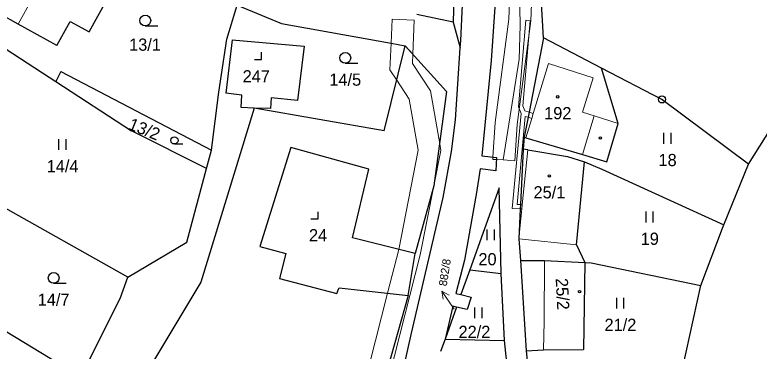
# Model space of a CAD drawing. Extents: x -739410 to -735662, y -942282 to -940043.
# Drawn here: x -738017.9 to -737914.5, y -941548.9 to -941502 of the extents above; entities that cross this region are included whole.
import ezdxf
from ezdxf.enums import TextEntityAlignment as Align

# ---------------------------------------------------------------- set-up
doc = ezdxf.new("R2010")
doc.units = 0
doc.header["$LTSCALE"] = 0.68
for name, color, linetype, lineweight in [('1', 7, 'Continuous', 25), ('13', 7, 'Continuous', 13), ('3', 7, 'Continuous', 25), ('4', 7, 'Continuous', 13), ('5', 7, 'Continuous', 25), ('7', 7, 'Continuous', 13), ('8', 7, 'Continuous', 25)]:
    doc.layers.add(name, color=color, linetype=linetype, lineweight=lineweight)
doc.layers.add('2', color=7, linetype='Continuous')

msp = doc.modelspace()

# ---------------------------------------------------------------- linework, layer by layer
at = {"layer": '1'}
for p, q in [((-737956.27, -941474.89), (-737956.99, -941503.08)), ((-737944.43, -941505.26), (-737945.75, -941484.01)), ((-737955.93, -941505.61), (-737955.53, -941496.64)), ((-737950.94, -941496.7), (-737951.7, -941508.41)), ((-738007.6, -941504.42), (-738004.51, -941498.81)), ((-737988.45, -941505.43), (-737987.03, -941500.71)), ((-737987.03, -941500.71), (-737980.87, -941503.23)), ((-738017.46, -941503.34), (-738019.6, -941502.11)), ((-737956.99, -941503.08), (-737962.06, -941502)), ((-738012.09, -941506.3), (-738017.46, -941503.34)), ((-738012.09, -941506.3), (-738010.26, -941502.95)), ((-738010.26, -941502.95), (-738007.6, -941504.42)), ((-737956.99, -941503.08), (-737956.01, -941506.61)), ((-737915.92, -941522.84), (-737904.39, -941504.29)), ((-738021.15, -941505.52), (-738014.09, -941510.1)), ((-737989.59, -941512.8), (-737988.45, -941505.43)), ((-737987.71, -941505.5), (-737988.6, -941512.93)), ((-737987.71, -941505.5), (-737977.73, -941506.41)), ((-737936.38, -941509.44), (-737944.43, -941505.26)), ((-737977.73, -941506.41), (-737978.64, -941513.98)), ((-737966.59, -941518.17), (-737963.66, -941506.35)), ((-737963.66, -941506.35), (-737957.9, -941512.7)), ((-737956.01, -941506.61), (-737955.93, -941505.61)), ((-737956.68, -941516.64), (-737956.01, -941506.61)), ((-737951.7, -941508.41), (-737953.03, -941521.67)), ((-737927.96, -941513.81), (-737936.38, -941509.44)), ((-737934.04, -941517.16), (-737936.38, -941509.44)), ((-738014.09, -941510.1), (-738012.26, -941511.3)), ((-738011.55, -941509.91), (-738012.26, -941511.3)), ((-738011.55, -941509.91), (-737990.58, -941520.89)), ((-738012.26, -941511.3), (-738001.72, -941518.17)), ((-737957.9, -941512.7), (-737959.66, -941525.86)), ((-737990.58, -941520.89), (-737989.59, -941512.8)), ((-737986.4, -941513.23), (-737988.6, -941512.93)), ((-737986.48, -941514.96), (-737986.4, -941513.23)), ((-737982.3, -941513.58), (-737982.38, -941515.08)), ((-737978.64, -941513.98), (-737982.3, -941513.58)), ((-737915.92, -941522.84), (-737927.96, -941513.81)), ((-737984.66, -941515.05), (-737992.08, -941539.27)), ((-737984.66, -941515.05), (-737986.48, -941514.96)), ((-737966.59, -941518.17), (-737984.66, -941515.05)), ((-737982.38, -941515.08), (-737984.66, -941515.05)), ((-737957.23, -941521.07), (-737956.68, -941516.64)), ((-737935.63, -941522.52), (-737934.04, -941517.16)), ((-737991.28, -941523.45), (-738001.72, -941518.17)), ((-737947.12, -941519.09), (-737947.26, -941520.75)), ((-737946.88, -941519.15), (-737947.12, -941519.09)), ((-737946.88, -941519.15), (-737939.02, -941521.48)), ((-737991.28, -941523.45), (-737990.58, -941520.89)), ((-737979.58, -941520.51), (-737983.87, -941534.28)), ((-737968.74, -941523.54), (-737979.58, -941520.51)), ((-737946.63, -941520.84), (-737947.26, -941520.75)), ((-737946.63, -941520.84), (-737941.08, -941521.74)), ((-737958.4, -941527.49), (-737957.23, -941521.07)), ((-737953.03, -941521.67), (-737950.96, -941521.9)), ((-737950.96, -941521.9), (-737951.05, -941523.76)), ((-737941.08, -941521.74), (-737938.72, -941522.52)), ((-737939.02, -941521.48), (-737935.63, -941522.52)), ((-737939.83, -941534.05), (-737938.72, -941522.52)), ((-737938.72, -941522.52), (-737936.33, -941523.54)), ((-738002.21, -941538.58), (-738029.62, -941523.14)), ((-737994.01, -941533.7), (-737991.28, -941523.45)), ((-737970.98, -941533.11), (-737968.74, -941523.54)), ((-737953.23, -941523.5), (-737953.77, -941526.76)), ((-737951.05, -941523.76), (-737953.23, -941523.5)), ((-737959.66, -941525.86), (-737962.29, -941535.26)), ((-737950.62, -941526.13), (-737954.7, -941537.56)), ((-737950.31, -941538.07), (-737950.62, -941526.13)), ((-737953.77, -941526.76), (-737955.44, -941536.18)), ((-737962.79, -941546.36), (-737958.4, -941527.49)), ((-737919.53, -941531.73), (-737919.35, -941531.28)), ((-737922.56, -941539.74), (-737919.53, -941531.73)), ((-737962.29, -941535.26), (-737970.98, -941533.11)), ((-737947.88, -941533.23), (-737947.64, -941536.23)), ((-738002.21, -941538.58), (-737994.01, -941533.7)), ((-737983.87, -941534.28), (-737980.26, -941535.26)), ((-737939.83, -941534.05), (-737938.68, -941536.52)), ((-737980.26, -941535.26), (-737981.16, -941538.76)), ((-737963.27, -941541.12), (-737962.29, -941535.26)), ((-738008.8, -941552.44), (-738035.99, -941536)), ((-737955.44, -941536.18), (-737956.63, -941540.84)), ((-737947.64, -941536.23), (-737944.28, -941536.23)), ((-737947.64, -941536.23), (-737946.84, -941548.83)), ((-737944.28, -941536.23), (-737938.68, -941536.52)), ((-737938.68, -941536.52), (-737938.87, -941548.66)), ((-737938.68, -941536.52), (-737937.79, -941536.55)), ((-737937.79, -941536.55), (-737922.56, -941539.74)), ((-737954.7, -941537.56), (-737955.93, -941541)), ((-737954.7, -941537.56), (-737950.31, -941538.07)), ((-738003.29, -941541.52), (-738002.21, -941538.58)), ((-737949.88, -941547.39), (-737950.31, -941538.07)), ((-737992.08, -941539.27), (-738002.35, -941556.34)), ((-737981.16, -941538.76), (-737973.15, -941540.85)), ((-737973.15, -941540.85), (-737972.94, -941540.24)), ((-737972.94, -941540.24), (-737972.83, -941540.07)), ((-737972.83, -941540.07), (-737963.27, -941541.12)), ((-737925.36, -941552.42), (-737922.56, -941539.74)), ((-738008.8, -941552.44), (-738003.29, -941541.52)), ((-737963.27, -941541.12), (-737968.25, -941558.78)), ((-737956.63, -941540.84), (-737955.93, -941541)), ((-737955.93, -941541), (-737954.49, -941541.34)), ((-737954.49, -941541.34), (-737955.06, -941543.06)), ((-737957.05, -941542.62), (-737958.13, -941547.19)), ((-737956.54, -941542.74), (-737958.13, -941547.19)), ((-737956.54, -941542.74), (-737957.05, -941542.62)), ((-737955.06, -941543.06), (-737956.54, -941542.74)), ((-737967.02, -941564.92), (-737962.79, -941546.36)), ((-737958.13, -941547.19), (-737958.74, -941548.9)), ((-737958.13, -941547.19), (-737949.88, -941547.39)), ((-737948.08, -941563.14), (-737949.88, -941547.39)), ((-737946.84, -941548.83), (-737944.44, -941548.68)), ((-737946.84, -941548.83), (-737946.69, -941550.15)), ((-737944.44, -941548.68), (-737938.87, -941548.66))]:
    msp.add_line(p, q, dxfattribs=at)
for points in [[(-737980.87, -941503.23), (-737965.61, -941506), (-737963.66, -941506.35)], [(-737944.43, -941505.26), (-737946.44, -941515.6), (-737946.58, -941516.29), (-737947.12, -941519.09)], [(-737947.26, -941520.75), (-737947.64, -941528.46), (-737947.67, -941529.06), (-737947.88, -941533.23)], [(-737936.33, -941523.54), (-737919.35, -941531.28), (-737915.92, -941522.84)]]:
    msp.add_lwpolyline(points, dxfattribs=at)
at = {"layer": '13'}
for points in [[(-737946.18, -941502.89), (-737946, -941498.04), (-737945.64, -941485.74), (-737945.75, -941484.01), (-737945.96, -941473.88), (-737945.13, -941473.11), (-737945.05, -941471.07), (-737944.75, -941470.11), (-737944.07, -941468.06), (-737943.25, -941467.49), (-737945.05, -941467.09), (-737946.29, -941465.87), (-737946.65, -941466.12), (-737948.13, -941470.51), (-737948.25, -941473.52), (-737947.7, -941503.53), (-737947.83, -941508.19), (-737950.02, -941522.24), (-737948.43, -941522.35), (-737948.09, -941517.32)], [(-737949.08, -941497.94), (-737949.26, -941502.63), (-737951.15, -941517.02), (-737951.48, -941521.84), (-737951.5, -941522.16), (-737950.97, -941522.19), (-737950.02, -941522.24), (-737947.83, -941508.19), (-737947.7, -941503.53), (-737948.25, -941473.52), (-737948.68, -941484.19)], [(-737965.48, -941502.64), (-737965.61, -941506), (-737963.66, -941506.35), (-737962.61, -941507.51), (-737962.42, -941502.76)], [(-737946.89, -941502.8), (-737947.91, -941514.83), (-737947.53, -941515.77), (-737948.77, -941529), (-737947.67, -941529.06), (-737947.64, -941528.46), (-737948.11, -941528.44), (-737946.97, -941516.17), (-737946.58, -941516.29), (-737946.44, -941515.6), (-737947.03, -941515.42), (-737947.31, -941514.73), (-737946.3, -941502.85)], [(-737973.73, -941570.83), (-737972.46, -941571.26), (-737970.78, -941571.73), (-737970.1, -941569.04), (-737968.25, -941558.78), (-737963.27, -941541.12), (-737962.29, -941535.26), (-737959.66, -941525.86), (-737958.87, -941519.98), (-737960.16, -941512.64), (-737962.64, -941508.83), (-737962.61, -941507.51), (-737963.66, -941506.35), (-737965.61, -941506), (-737965.78, -941509.69), (-737964.84, -941511.13), (-737963.1, -941513.8), (-737961.87, -941520.87), (-737964.56, -941534.7), (-737966.11, -941540.81)], [(-737946.44, -941515.6), (-737946.58, -941516.29), (-737946.06, -941516.45), (-737945.85, -941515.78)], [(-737959.66, -941525.86), (-737958.71, -941520.91), (-737958.87, -941519.98)], [(-737961.57, -941535.45), (-737959.66, -941525.86), (-737962.29, -941535.26), (-737963.27, -941541.12), (-737968.25, -941558.78), (-737970.1, -941569.04)], [(-737947.64, -941528.46), (-737947.67, -941529.06), (-737947.46, -941529.07), (-737947.4, -941528.47)]]:
    msp.add_lwpolyline(points, close=True, dxfattribs=at)
at = {"layer": '3'}
for p, q in [((-737999.803, -941503.58), (-737998.053, -941503.58)), ((-737971.993, -941508.78), (-737970.243, -941508.78)), ((-737927.691, -941519.98), (-737927.691, -941518.48)), ((-737926.69, -941519.98), (-737926.69, -941518.48)), ((-738011.811, -941520.84), (-738011.811, -941519.34)), ((-738010.81, -941520.84), (-738010.81, -941519.34)), ((-737995.755, -941520.02), (-737994.583, -941520.02)), ((-737930.171, -941530.94), (-737930.171, -941529.44)), ((-737929.17, -941530.94), (-737929.17, -941529.44)), ((-737952.261, -941533.43), (-737952.261, -941531.93)), ((-737951.26, -941533.43), (-737951.26, -941531.93)), ((-738012.543, -941539.42), (-738010.793, -941539.42)), ((-737934.251, -941542.92), (-737934.251, -941541.42)), ((-737933.25, -941542.92), (-737933.25, -941541.42)), ((-737953.961, -941544.29), (-737953.961, -941542.79)), ((-737952.96, -941544.29), (-737952.96, -941542.79))]:
    msp.add_line(p, q, dxfattribs=at)
for points in [[(-737984.641, -941508.25), (-737983.64, -941508.25), (-737983.64, -941507.25)], [(-737976.781, -941530.45), (-737975.78, -941530.45), (-737975.78, -941529.45)]]:
    msp.add_lwpolyline(points, dxfattribs=at)
for centre, radius in [((-737999.8029, -941502.8298), 0.75), ((-737971.9929, -941508.0298), 0.75), ((-737995.7552, -941519.5174), 0.5025), ((-738012.5429, -941538.6698), 0.75)]:
    msp.add_circle(centre, radius, dxfattribs=at)
at = {"layer": '4'}
for p, q in [((-738017.46, -941503.34), (-738012.57, -941494.37)), ((-737945.85, -941515.78), (-737943.72, -941508.79)), ((-737943.72, -941508.79), (-737937.53, -941510.81)), ((-737939, -941515.61), (-737937.53, -941510.81)), ((-737946.06, -941516.45), (-737945.85, -941515.78)), ((-737937.38, -941516.09), (-737939, -941515.61)), ((-737946.88, -941519.15), (-737946.06, -941516.45)), ((-737939.02, -941521.48), (-737937.38, -941516.09)), ((-737934.04, -941517.16), (-737937.38, -941516.09)), ((-737946.63, -941520.84), (-737947.4, -941528.47)), ((-737947.46, -941529.07), (-737947.88, -941533.23)), ((-737947.4, -941528.47), (-737947.46, -941529.07)), ((-737947.88, -941533.23), (-737939.83, -941534.05)), ((-737944.28, -941536.23), (-737944.36, -941544.74)), ((-737944.36, -941544.74), (-737944.44, -941548.68))]:
    msp.add_line(p, q, dxfattribs=at)
at = {"layer": '5'}
for centre in [(-737942.4568, -941513.4492), (-737936.5268, -941519.1792), (-737943.6168, -941524.4692), (-737939.4168, -941540.5892)]:
    msp.add_circle(centre, 0.175, dxfattribs=at)
at = {"layer": '7'}
msp.add_line((-737958.548, -941540.532), (-737958.403, -941541.642), dxfattribs=at)
msp.add_lwpolyline([(-737956.87, -941543.02), (-737958.548, -941540.532), (-737957.573, -941541.082)], dxfattribs=at)
at = {"layer": '8'}
for radius in [0.5, 0.0303]:
    msp.add_circle((-737927.96, -941513.8099), radius, dxfattribs=at)

# ---------------------------------------------------------------- texts
at = {"layer": '2'}
for s, p in [('13/1', (-737999.839, -941507.035)), ('247', (-737984.369, -941511.445)), ('14/5', (-737971.999, -941511.905)), ('192', (-737942.449, -941516.575)), ('18', (-737927.179, -941523.105)), ('14/4', (-738011.299, -941523.965)), ('25/1', (-737943.609, -941527.595)), ('24', (-737975.779, -941533.575)), ('19', (-737929.659, -941534.065)), ('20', (-737952.219, -941536.915)), ('14/7', (-738012.549, -941542.545)), ('21/2', (-737933.739, -941546.045)), ('22/2', (-737954.039, -941547.035))]:
    msp.add_text(s, height=1.7, dxfattribs=at).set_placement(p, align=Align.CENTER)
for s, height, rotation, p in [('13/2', 1.7, 338, (-738000.2469, -941518.7387)), ('882/8', 1.139, 81, (-737957.6016, -941537.9991)), ('25/2', 1.7, 273, (-737942.6324, -941540.9445))]:
    msp.add_text(s, height=height, rotation=rotation, dxfattribs=at).set_placement(p, align=Align.CENTER)

doc.saveas('drawing.dxf')
